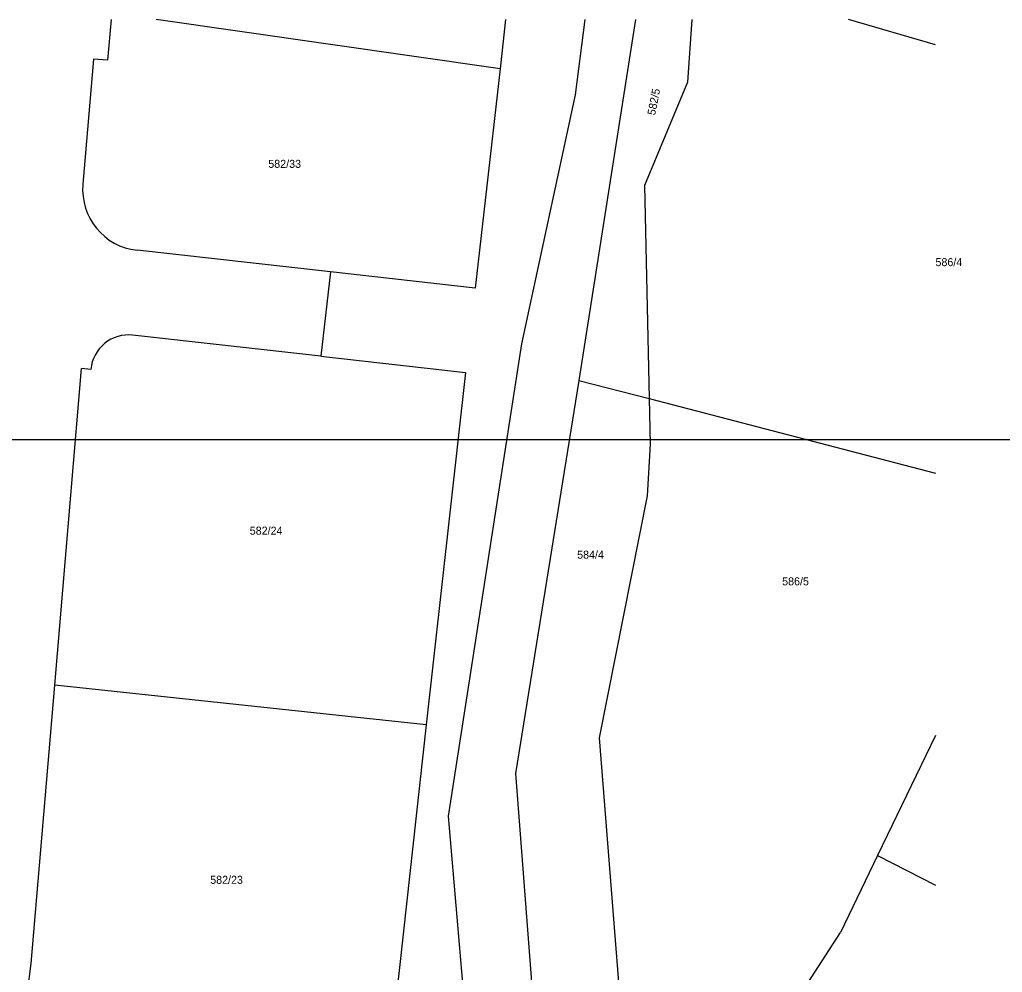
# Model space of a CAD drawing. Extents: x -770973 to -770265, y -1049936 to -1049427.
# Drawn here: x -770527.3 to -770423, y -1049529.2 to -1049428.1 of the extents above; entities that cross this region are included whole.
import ezdxf

# ---------------------------------------------------------------- set-up
doc = ezdxf.new("R2010")
doc.units = 0
for name, color, linetype in [('Vrstva 1', 7, 'Continuous'), ('Vrstva 14', 7, 'Continuous'), ('Vrstva 63', 7, 'Continuous')]:
    doc.layers.add(name, color=color, linetype=linetype)

msp = doc.modelspace()

# ---------------------------------------------------------------- linework, layer by layer
at = {"layer": 'Vrstva 1'}
for p, q in [((-770517.59, -1049428.06), (-770517.99, -1049432.37)), ((-770476.31, -1049433.27), (-770512.84, -1049428.06)), ((-770475.73, -1049428.06), (-770476.31, -1049433.27)), ((-770467.32, -1049428.06), (-770468.32, -1049436.05)), ((-770461.93, -1049428.06), (-770467.95, -1049466.37)), ((-770455.94, -1049428.06), (-770456.42, -1049434.69)), ((-770430.07, -1049430.75), (-770439.3, -1049428.06)), ((-770519.49, -1049432.24), (-770520.61, -1049445.55)), ((-770517.99, -1049432.37), (-770519.49, -1049432.24)), ((-770476.31, -1049433.27), (-770478.97, -1049456.58)), ((-770456.42, -1049434.69), (-770460.97, -1049445.69)), ((-770468.32, -1049436.05), (-770474.03, -1049462.49)), ((-770460.97, -1049445.69), (-770460.48, -1049468.31)), ((-770494.32, -1049454.86), (-770514.86, -1049452.56)), ((-770494.32, -1049454.86), (-770495.33, -1049463.8)), ((-770478.97, -1049456.58), (-770494.32, -1049454.86)), ((-770495.33, -1049463.8), (-770515.33, -1049461.56)), ((-770474.03, -1049462.49), (-770481.81, -1049512.66)), ((-770495.33, -1049463.8), (-770479.97, -1049465.53)), ((-770523.59, -1049498.74), (-770520.75, -1049465.12)), ((-770519.76, -1049465.2), (-770520.75, -1049465.12)), ((-770479.97, -1049465.53), (-770484.17, -1049502.96)), ((-770467.95, -1049466.37), (-770474.68, -1049508.11)), ((-770467.95, -1049466.37), (-770460.48, -1049468.31)), ((-770460.48, -1049468.31), (-770460.38, -1049473.14)), ((-770460.48, -1049468.31), (-770430.07, -1049476.22)), ((-770460.38, -1049473.14), (-770460.7, -1049478.63)), ((-770460.7, -1049478.63), (-770465.79, -1049504.34)), ((-770526.08, -1049528.32), (-770523.59, -1049498.74)), ((-770484.17, -1049502.96), (-770523.59, -1049498.74)), ((-770484.17, -1049502.96), (-770488.51, -1049542.82)), ((-770465.79, -1049504.34), (-770462.96, -1049540.28)), ((-770430.07, -1049504.1), (-770436.22, -1049516.84)), ((-770474.68, -1049508.11), (-770471.77, -1049545.62)), ((-770481.81, -1049512.66), (-770479.21, -1049543.24)), ((-770436.22, -1049516.84), (-770440.17, -1049525.01)), ((-770436.22, -1049516.84), (-770430.07, -1049519.99)), ((-770445.89, -1049533.82), (-770440.17, -1049525.01)), ((-770526.48, -1049531.34), (-770526.08, -1049528.32))]:
    msp.add_line(p, q, dxfattribs=at)
for centre, radius, start, end in [((-770514.13, -1049446.1), 6.5, 175.1641, 263.557), ((-770515.76, -1049465.55), 4.01, 83.8391, 174.9788)]:
    msp.add_arc(centre, radius, start, end, dxfattribs=at)
at = {"layer": 'Vrstva 63'}
msp.add_lwpolyline([(-770858.67, -1049892.7), (-770264.67, -1049892.7), (-770264.67, -1049472.7), (-770858.67, -1049472.7), (-770858.67, -1049892.7)], dxfattribs=at)

# ---------------------------------------------------------------- texts
at = {"layer": 'Vrstva 14'}
msp.add_text('582/5', height=0.85, rotation=78.8883, dxfattribs=at).set_placement((-770459.85, -1049438.26))
for s, p in [('582/33', (-770500.92, -1049443.8)), ('586/4', (-770430.08, -1049454.24)), ('582/24', (-770502.89, -1049482.76)), ('584/4', (-770468.13, -1049485.31)), ('586/5', (-770446.36, -1049488.14)), ('582/23', (-770507.09, -1049519.84))]:
    msp.add_text(s, height=0.85, dxfattribs=at).set_placement(p)

doc.saveas('drawing.dxf')
